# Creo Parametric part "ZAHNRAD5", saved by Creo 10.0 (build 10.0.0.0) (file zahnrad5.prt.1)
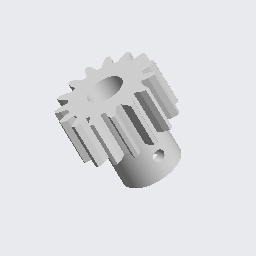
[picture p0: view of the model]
Units: millimeter Newton Second (mmNs); MM, TONNE, SECS

Created from: PRT0003.PRT

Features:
  1. coordinate system "29601500"
  2. imported feature "Import-ke ID 5"
  3. datum plane "DTM1"
  4. datum plane "DEFAULT_1"
  5. extruded cut "Profil 1"
  6. datum axis "A_2"
  7. hole "Bohrung 1"

Other named items: NOTE_0

Notes: 29601500

Surfaces: 63 plane, 35 cylinder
